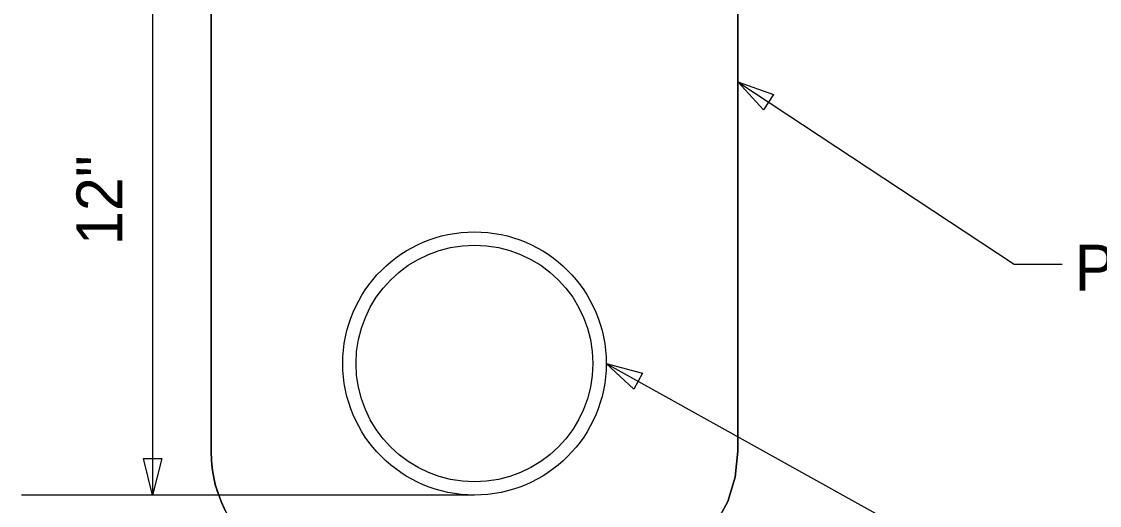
# Model space of a CAD drawing. Extents: x 10378.8 to 10426.8, y 9885.5 to 9932.9.
# Drawn here: x 10386.2 to 10410.75, y 9902.24 to 9913.27 of the extents above; entities that cross this region are included whole.
import ezdxf

# ---------------------------------------------------------------- set-up
doc = ezdxf.new("R2010")
doc.units = 0
for name, color, linetype in [('Default', 7, 'Continuous'), ('G-ANNO-TEXT', 7, 'Continuous'), ('G-DETL-OTLN', 7, 'Continuous'), ('G-DETL-PATT', 7, 'Continuous')]:
    doc.layers.add(name, color=color, linetype=linetype)

# ---------------------------------------------------------------- blocks, each defined once
blk = doc.blocks.new('TERARR')
at = {"layer": 'Default'}
blk.add_lwpolyline([(-0.667, 0.167), (0, 0), (-0.667, -0.167)], close=True, dxfattribs=at)

msp = doc.modelspace()

# ---------------------------------------------------------------- linework, layer by layer
at = {"layer": 'Default'}
msp.add_line((10389.326, 9902.473), (10388.876, 9902.473), dxfattribs=at)
at = {"layer": 'G-ANNO-TEXT'}
for p, q in [((10389.187, 9917.439), (10389.187, 9902.473)), ((10396.518, 9902.473), (10386.201, 9902.473))]:
    msp.add_line(p, q, dxfattribs=at)
for points in [[(10402.519, 9911.889), (10408.812, 9907.74), (10409.904, 9907.74)], [(10399.518, 9905.473), (10407.611, 9900.969), (10409.439, 9900.969)]]:
    msp.add_lwpolyline(points, dxfattribs=at)
at = {"layer": 'G-DETL-OTLN'}
for p, q in [((10402.518, 9903.473), (10402.518, 9917.722)), ((10390.518, 9917.47), (10390.518, 9903.473))]:
    msp.add_line(p, q, dxfattribs=at)
msp.add_lwpolyline([(10390.837, 9902.124), (10390.746, 9902.325), (10390.672, 9902.538), (10390.614, 9902.708), (10390.549, 9903.035), (10390.526, 9903.251), (10390.518, 9903.473), (10390.518, 9917.47), (10402.518, 9917.721), (10402.518, 9903.473), (10402.452, 9902.878), (10402.29, 9902.325), (10402.025, 9901.839)], dxfattribs=at)
for radius in [3, 2.698]:
    msp.add_circle((10396.518, 9905.473), radius, dxfattribs=at)
msp.add_arc((10393.518, 9903.473), 3, 180, 270, dxfattribs=at)
at = {"layer": 'G-DETL-PATT'}
for points in [[(10402.025, 9901.839), (10402.29, 9902.325), (10402.452, 9902.878), (10402.518, 9903.473), (10402.518, 9917.721), (10390.518, 9917.47), (10390.518, 9903.473)], [(10390.518, 9903.473), (10390.526, 9903.251), (10390.549, 9903.035), (10390.614, 9902.708), (10390.672, 9902.538), (10390.746, 9902.325), (10390.837, 9902.124)]]:
    msp.add_lwpolyline(points, dxfattribs=at)
msp.add_circle((10396.518, 9905.473), 3, dxfattribs=at)

# ---------------------------------------------------------------- block references
at = {"layer": 'G-ANNO-TEXT'}
for p, xscale, yscale, rotation in [((10402.519, 9911.889), 1.2499199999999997, 1.2499200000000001, 146.60008904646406), ((10399.518, 9905.473), 1.2499200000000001, 1.2499200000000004, 150.90219371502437), ((10389.187, 9902.473), 1.24992, 1.24992, -90)]:
    msp.add_blockref('TERARR', p, dxfattribs=dict(at, xscale=xscale, yscale=yscale, rotation=rotation))

# ---------------------------------------------------------------- texts
msp.add_text('12"', height=1.044, rotation=90, dxfattribs=at).set_placement((10388.496, 9908.168))
msp.add_text('PEA GRAVEL BACKFILL', height=1.044, dxfattribs=at).set_placement((10410.187, 9907.135))

doc.saveas('drawing.dxf')
